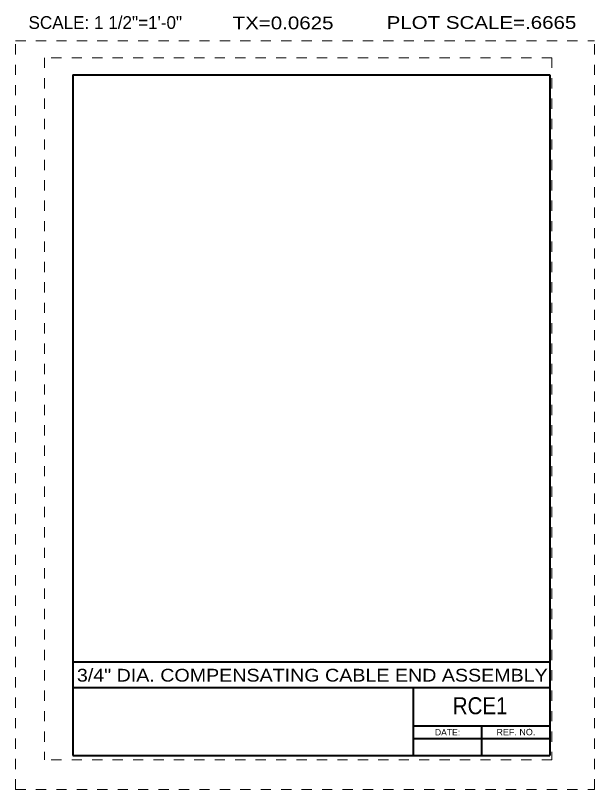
# Model space of a CAD drawing. Extents: x 1370.02 to 1375.68, y -905.51 to -897.93.
import ezdxf
from ezdxf.enums import TextEntityAlignment as Align

# ---------------------------------------------------------------- set-up
doc = ezdxf.new("R2010")
doc.units = 0
doc.header["$LTSCALE"] = 0.05
doc.linetypes.add('DOTTED', pattern=[1.5, 0.3, -1.2])
for name, color, linetype in [('57', 7, 'Continuous'), ('58', 7, 'Continuous'), ('59', 7, 'Continuous'), ('9', 7, 'Continuous')]:
    doc.layers.add(name, color=color, linetype=linetype)
for name, color, linetype, lineweight in [('61', 7, 'DOTTED', 13), ('62', 7, 'DOTTED', 13), ('63', 7, 'Continuous', 40)]:
    doc.layers.add(name, color=color, linetype=linetype, lineweight=lineweight)

msp = doc.modelspace()

# ---------------------------------------------------------------- linework, layer by layer
at = {"layer": '61'}
for p, q in [((1375.266, -898.34375), (1370.29908, -898.34375)), ((1370.29908, -898.34375), (1370.29908, -905.22208)), ((1375.266, -898.34375), (1375.266, -905.22208)), ((1375.266, -905.22208), (1370.29908, -905.22208))]:
    msp.add_line(p, q, dxfattribs=at)
at = {"layer": '62'}
for p, q in [((1370.01575, -905.51208), (1370.01575, -898.17875)), ((1370.01575, -898.17875), (1375.68267, -898.17875)), ((1375.68267, -905.51208), (1375.68267, -898.17875)), ((1370.01575, -905.51208), (1375.68267, -905.51208))]:
    msp.add_line(p, q, dxfattribs=at)
at = {"layer": '63'}
for p, q in [((1370.57825, -898.51208), (1370.57825, -905.17875)), ((1370.57825, -898.51208), (1375.24517, -898.51208)), ((1375.24517, -898.51208), (1375.24517, -905.17875)), ((1370.57825, -904.26208), (1375.24517, -904.26208)), ((1370.57825, -904.51208), (1375.24517, -904.51208)), ((1373.91175, -905.17875), (1373.91175, -904.51208)), ((1373.91175, -904.88708), (1375.24517, -904.88708)), ((1374.5785, -905.17875), (1374.5785, -904.88708)), ((1373.91175, -905.01208), (1375.24517, -905.01208)), ((1370.57825, -905.17875), (1375.24517, -905.17875))]:
    msp.add_line(p, q, dxfattribs=at)

# ---------------------------------------------------------------- texts
at = {"layer": '57', "width": 1.15}
msp.add_text('3/4" DIA. COMPENSATING CABLE END ASSEMBLY', height=0.125, dxfattribs=at).set_placement((1372.92075, -904.45483), align=Align.CENTER)
at = {"layer": '58', "width": 0.9}
msp.add_text('RCE1', height=0.1667, dxfattribs=at).set_placement((1374.56337, -904.77475), align=Align.CENTER)
at = {"layer": '59', "width": 1.05}
msp.add_text('REF. NO.', height=0.06258, dxfattribs=at).set_placement((1374.91321, -904.98058), align=Align.CENTER)
at = {"layer": '59'}
msp.add_text('DATE:', height=0.06256, dxfattribs=at).set_placement((1374.24425, -904.98275), align=Align.CENTER)
at = {"layer": '9'}
msp.add_text('SCALE: 1 1/2"=1\'-0"', height=0.125, dxfattribs=at).set_placement((1370.8945, -898.06167), align=Align.CENTER)
at = {"layer": '9', "width": 1.2}
for s, p in [('TX=0.0625', (1372.6345, -898.06575)), ('PLOT SCALE=.6665', (1374.57637, -898.06167))]:
    msp.add_text(s, height=0.125, dxfattribs=at).set_placement(p, align=Align.CENTER)

doc.saveas('drawing.dxf')
